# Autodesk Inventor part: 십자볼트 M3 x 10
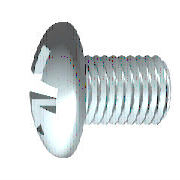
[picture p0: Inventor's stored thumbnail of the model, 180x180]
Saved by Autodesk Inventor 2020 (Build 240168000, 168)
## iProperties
Created: 2012-02
Part Number: 십자볼트 M3 x 10
Material: 스테인리스강
Description: 십자 오목 머리 나사
Document SubType Name: Modeling
Standard: KS B 1023
Designer: mduedu
Standards Organization: KS
Language: ko-KR
Size Designation: A  M 3 x 10 - H
Categories: <MemberInstance><Categories><Category DisplayName="조임쇠" InternalName="e4da775c-781d-43d5-af7c-5136215cf5a6" Mnemonic="FSTN"><Category DisplayName="볼트" InternalN
Density: 1 g/cm^3
Appearance: 반광택
IsCustomPart: 0
Author: mduedu
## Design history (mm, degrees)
workplane "Work Plane3"
sketch "스케치2"
  geometry: L1 (-3.72, 0)-(3.72, 0) reference; L2 (0, -3.72)-(0, 3.72) reference; L3 (0, 1.5)-(0, 0); L4 (0, 0)-(1.5, 0); L5 (0, 0)-(1.879, 1.879); L6 (0.253, 1.479)-(0.261, 0.456); L7 (1.479, 0.253)-(0.456, 0.261); L8 (0.253, -1.479)-(0.261, -0.456); L9 (1.479, -0.253)-(0.456, -0.261); L10 (-0.253, 1.479)-(-0.261, 0.456); L11 (-1.479, 0.253)-(-0.456, 0.261); L12 (-1.479, -0.253)-(-0.456, -0.261); L13 (-0.253, -1.479)-(-0.261, -0.456); A1 r 0.45 centre (0, 0) between (0.45, 0) and (0, 0.45); A2 r 1.5 centre (0, 0) between (1.5, 0) and (1.479, 0.253); A3 r 1.5 centre (0, 0) between (0.253, 1.479) and (0, 1.5); A4 r 1.5 centre (0, 0) between (1.479, 0.253) and (0.253, 1.479); A5 r 1.5 centre (0, 0) between (0, -1.5) and (0.253, -1.479); A6 r 1.5 centre (0, 0) between (0.253, -1.479) and (1.479, -0.253); A7 r 1.5 centre (0, 0) between (1.479, -0.253) and (1.5, 0); A8 r 1.5 centre (0, 0) between (-1.479, 0.253) and (-1.5, 0); A9 r 1.5 centre (0, 0) between (-0.253, 1.479) and (-1.479, 0.253); A10 r 1.5 centre (0, 0) between (0, 1.5) and (-0.253, 1.479); A11 r 1.5 centre (0, 0) between (-1.5, 0) and (-1.479, -0.253); A12 r 1.5 centre (0, 0) between (-1.479, -0.253) and (-0.253, -1.479); A13 r 1.5 centre (0, 0) between (-0.253, -1.479) and (0, -1.5); A14 r 0.525 centre (0, 0) between (0.525, 0) and (0, 0.525); A15 r 0.197 centre (0.457, 0.457) between (0.261, 0.456) and (0.456, 0.261); A16 r 0.197 centre (0.457, -0.457) between (0.456, -0.261) and (0.261, -0.456); A17 r 0.197 centre (-0.457, 0.457) between (-0.456, 0.261) and (-0.261, 0.456); A18 r 0.197 centre (-0.457, -0.457) between (-0.261, -0.456) and (-0.456, -0.261); 1 further point
  constraints: 38 point on circle, 22 end point, 19 symmetric about line, 18 centre point, 4 coincident, 3 collinear, 3 point on line, 3 tangent, 1 perpendicular, 21 other
  dimensions: "d4" = 45 deg angle of L5 L4; "d5" = 0.9 diameter of A1 (= 0.3 x SDM); "d6" = 3 diameter of A4 (= SDM); "d7" = 0.2525 distance from line of L6.start L3 (= 0.5 x SBR); "d14" = 1.05 diameter of A14 (= 0.35 x SDM)
extrude "슬롯" join sketch "스케치2" taper "d15" = 5 deg; stored distance "d54" = 10
revolve "절단부" stored, may be unused: angle "d56" = 90 deg
revolve "본체" stored, may be unused: angle "d18" = 90 deg
workplane "Work Plane1"
body "Solid1"
sketch "스케치1"
  geometry: L1 (10, 0)-(10, 1.5); L2 (10, 1.5)-(1, 1.5); L3 (3.962, 5.08)-(3.962, 5.08); L4 (-2.4, 0)-(-2.4, 2.59); L5 (-2.2, 1.4)-(-1.036, 0.82); L6 (-1.036, 0.82)-(-0.6, 0); L7 (-0.6, 0)-(10, 0); L8 (-5.105, 0)-(12.517, 0) reference; L9 (0, -1.016)-(0, 6.096) reference; L10 (-2.2, 1.4)-(-2.4, 1.5); L11 (-1.636, 2.657)-(-2.4, 2.59); L12 (-1.636, 2.657)-(0, 2.8); L13 (0, 2.8)-(0, 1.347); L14 (0, 1.347)-(0.693, 1.347); L15 (0.693, 1.347)-(1, 1.5); L16 (1, 1.5)-(0, 1.5); A1 r 5 centre (2.6, 0) between (-1.636, 2.657) and (-2.4, 0)
  constraints: 28 end point, 5 point on line, 4 collinear, 4 point on circle, 3 parallel, 2 perpendicular, 1 centre point, 1 horizontal, 1 tangent
  dimensions: "d1" = 3 diameter of L2 L7 (= GD); "d2" = 1.8 distance from line of L6.end L4 (= STI); "d11" = 3 diameter of L10.end L7 (= SDM); "d12" = 62 deg angle of L6 L7; "d13" = 26.5 deg angle of L5 L7; "d17" = 5.6 diameter of L12.end L7 (= KOD); "d19" = 5 deg angle of L12 L7 (= KEWI); "d20" = 2.4 distance between parallel lines of L4 L13 (= KOH); "d21" = 5 radius of A1 (= KR); "d23" = 2.6935 diameter of L14 L7 (= BDM); "d24" = 9 distance of L1.end L2.end (= GEL); "d25" = 0.30673 horizontal distance of L14.end L2.end (= GAL); "d28" = 10 distance between parallel lines of L1 L13 (= NLG)
fillet "모깎기1" dims "d29" = 1.2 (= RR)
fillet "모깎기2" dims "d16" = 0.101 (= 0.2 x SBR)
feature "스레드" dims "d8" = 9 (= GEL), "d9" = 0
chamfer "모따기1" distance "d26" = 0.30673 (= -0.5 x SPD + 0.5 x GD); stored, may be unused: second distance "d27" = 0.30683 (computed from GUL), angle "d78" = 45 deg
other parameters: "GD" = 3 (= NND) [user parameter; used in 2 equation terms], "NLG" = 10 [user parameter; used in 1 equation term], "GEL" = 9 [user parameter; used in 2 equation terms], "KOD" = 5.6 [user parameter; used in 1 equation term], "KOH" = 2.4 [user parameter; used in 2 equation terms], "SDM" = 3 [user parameter; used in 4 equation terms], "STI" = 1.8 [user parameter; used in 1 equation term], "SBR" = 0.505 [user parameter; used in 2 equation terms], "GAL" = 0.30673 (= 0.61345 x PTC) [user parameter; used in 1 equation term], "SPD" = 2.38655 (= NND - 1.2269 x PTC) [user parameter; used in 1 equation term], "KEWI" = 5 deg [user parameter; used in 1 equation term], "d3" = -2.4 (= -KOH), "d10" = 0, "KR" = 5 [user parameter; used in 1 equation term], "BDM" = 2.6935 [user parameter; used in 1 equation term], "GUL" = 0.30673 (= 0.61345 x PTC) [user parameter; used in 1 equation term], "RR" = 1.2 [user parameter; used in 1 equation term], "d79" = 0, "d80" = 0, "PTC" = 0.5 [user parameter; used in 5 equation terms], "THREADDIA" = 3 [user parameter; used in 1 equation term], "TOA" = 30 deg [user parameter], "NND" = 3 [user parameter; used in 2 equation terms], "GD1" = 2.38655 (= THREADDIA - 1.2269 x PTC) [user parameter]
